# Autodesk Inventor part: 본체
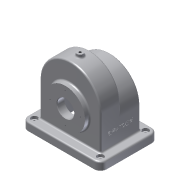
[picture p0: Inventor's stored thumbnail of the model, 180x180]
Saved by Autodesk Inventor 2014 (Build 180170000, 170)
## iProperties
Created: 2017-11
Part Number: 본체
Material: 알루미늄 6061
Document SubType Name: Modeling
Designer: user
Density: 2.71 g/cm^3
Appearance: 알루미늄 - 평지
Mass: 1124.69 g
Surface Area: 1251.26 cm^2
Volume: 415.016 cm^3
Author: user
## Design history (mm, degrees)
sketch "스케치2"
  geometry: L1 (-58, 0)-(-58, -65); L2 (58, 0)-(58, -65); L3 (58, -65)-(-58, -65); A1 r 58 centre (0, 0) between (58, 0) and (-58, 0); 1 further point
  constraints: 6 end point, 2 point on circle, 2 tangent, 1 centre point, 1 coincident, 1 parallel, 1 perpendicular, 1 vertical
  dimensions: "d2" = 116 diameter of A1; "d3" = 65 distance of L1.start L1.end
extrude "돌출1" new body sketch "스케치2" distance "d4" = 38; taper "d5" = 0 deg
sketch "스케치3"
  geometry: L1 (0, 0)-(0, -23); L2 (-58, 0)-(-58, -65) reference; L3 (-58, -65)-(58, -65) reference; L4 (58, -65)-(58, 0) reference; A1 r 58 centre (0, -23) between (58, -23) and (-58, -23)
  constraints: 2 end point, 2 point on circle, 2 point on line, 1 centre point, 1 coincident, 1 vertical
  dimensions: "d7" = 23 distance of L1.start L1.end; "d8" = 116 diameter of A1
extrude "돌출2" join sketch "스케치3" distance "d9" = 38; taper "d10" = 0 deg
sketch "스케치4"
  geometry: L1 (-17, -93)-(133, -93); L2 (133, -93)-(133, 17); L3 (133, 17)-(-17, 17); L4 (-17, 17)-(-17, -93); L5 (-17, -93)-(133, 17); L6 (133, -93)-(-17, 17); 1 further point
  constraints: 12 end point, 2 midpoint, 2 parallel, 1 horizontal, 1 perpendicular
  dimensions: "d11" = 110 distance of L3.end L1.start; "d12" = 150 distance of L1.start L1.end
extrude "돌출3" join sketch "스케치4" distance "d13" = 15; taper "d14" = 0 deg
fillet "모깎기1" dims "d15" = 12
sketch "스케치5"
  geometry: L1 (63, -80)-(-63, -80) reference; L2 (0, -80)-(0, -15); C1 r 37.5 at (0, -15); 1 further point
  constraints: 2 end point, 1 centre point, 1 coincident, 1 midpoint, 1 perpendicular
  dimensions: "d17" = 65 distance of L2.start L2.end; "d18" = 75 diameter of C1
extrude "돌출4" join sketch "스케치5" distance "d19" = 9; taper "d20" = 0 deg
sketch "스케치6"
  geometry: L1 (63, -80)-(-63, -80) reference; L2 (0, -80)-(0, -15); C1 r 31 at (0, -15); 1 further point
  constraints: 2 end point, 1 centre point, 1 coincident, 1 midpoint, 1 perpendicular
  dimensions: "d21" = 65 distance of L2.start L2.end; "d22" = 62 diameter of C1
extrude "돌출5" join sketch "스케치6" distance "d23" = 10; taper "d24" = 0 deg
fillet "모깎기2" dims "d16" = 3
node "작업 평면1"
sketch "스케치8"
  geometry: L1 (-53, 0)-(-53, -89.092); L2 (-53, -89.092)-(53, -89.092); L3 (53, -89.092)-(53, 0); A1 r 53 centre (0, 0) between (53, 0) and (-53, 0); 1 further point
  constraints: 6 end point, 2 point on circle, 2 tangent, 1 centre point, 1 coincident, 1 perpendicular, 1 vertical
  dimensions: "d39" = 106 diameter of A1
extrude "돌출6" cut sketch "스케치8" distance "d40" = 28; taper "d41" = 0 deg
sketch "스케치9"
  geometry: L1 (0, 0)-(0, -23); L2 (-53, -23)-(-53, -80); L3 (-53, -80)-(53, -80); L4 (53, -80)-(53, -23); L5 (-63, -80)-(-75, -80) reference; L6 (-63, -80)-(63, -80) reference; L7 (75, -80)-(63, -80) reference; L8 (63, -80)-(75, -80) reference; L9 (63, -80)-(-63, -80) reference; L10 (-75, -80)-(-63, -80) reference; A1 r 53 centre (0, -23) between (53, -23) and (-53, -23)
  constraints: 8 end point, 2 point on circle, 2 tangent, 1 centre point, 1 coincident, 1 parallel, 1 perpendicular, 1 vertical
  dimensions: "d42" = 23 distance of L1.start L1.end; "d43" = 106 diameter of A1
extrude "돌출7" cut sketch "스케치9" distance "d44" = 38; taper "d45" = 0 deg
sketch "스케치7"
  geometry: L1 (-10.374, 37.577)-(21.813, -22.429); L2 (58, 3)-(58, 35) reference; L3 (22.5, 41)-(22.5, 47) reference; L4 (35, -3)-(35, -35) reference; L5 (16, -41)-(16, -48) reference; L6 (35, -3)-(35, -35) reference; L7 (-80, -55)-(-80, -43) reference; L8 (-80, -43)-(-80, -55) reference; L9 (-80, -43)-(-80, 43) reference; L10 (-80, 55)-(-80, 43) reference; L11 (-80, 43)-(-80, 55) reference; L12 (-80, 43)-(-80, -43) reference; L13 (0, 38)-(-62, 38) reference; L14 (0, 38)-(0, 38) reference; L15 (-62, 38)-(0, 38) reference; L16 (25.5, 38)-(-55.5, 38) reference; L17 (55, 0)-(3.63, 0) reference; L18 (22.5, 47)-(-52.5, 47) reference; L19 (-46, -48)-(16, -48) reference; L20 (-15, -48)-(-15, 47); L21 (1, 47)-(1, 33); L22 (1, 33)-(-15, 33); L23 (1, -48)-(1, -33); L24 (1, -33)-(-15, -33); A1 r 3 centre (55, 35) between (58, 35) and (55, 38) reference; A2 r 3 centre (25.5, 41) between (22.5, 41) and (25.5, 38) reference; A3 r 3 centre (38, -3) between (38, 0) and (35, -3) reference; A4 r 3 centre (55, 3) between (55, 0) and (58, 3) reference; A5 r 3 centre (32, -35) between (32, -38) and (35, -35) reference; A6 r 3 centre (-55.5, 41) between (-55.5, 38) and (-52.5, 41) reference; 1 further point
  constraints: 12 end point, 4 point on line, 3 perpendicular, 2 midpoint, 1 parallel
  dimensions: "d30" = 32 diameter of L21 L20; "d31" = 32 diameter of L23 L20; "d32" = 14 distance of L21.start L21.end; "d33" = 15 distance of L23.start L23.end
revolve "회전1" sketch "스케치7" stored, may be unused: angle "d34" = 90 deg
chamfer "모따기1" distance "d35" = 1; stored, may be unused: second distance "d36" = 2, angle "d37" = 45 deg
fillet "모깎기3" dims "d46" = 3
sketch "스케치10"
  geometry: L1 (53, 19)-(64, 19); L2 (0, 38)-(55, 38) reference; L3 (64, 19)-(64, 13); L4 (64, 13)-(53, 13); L5 (-80, -30)-(-80, 30) reference; L6 (53, 13)-(53, 19); L7 (53, 8)-(53, 30) reference; 2 further points
  constraints: 9 end point, 2 perpendicular, 1 collinear, 1 horizontal, 1 parallel
  dimensions: "d47" = 19 distance between parallel lines of L1 L2; "d48" = 12 diameter of L4 L1; "d49" = 144 distance between parallel lines of L3 L5
revolve "회전2" sketch "스케치10" stored, may be unused: angle "d50" = 90 deg
fillet "모깎기4" dims "d51" = 3
hole "구멍1" diameter "d54" = 4.459; stored, may be unused: countersink angle "d58" = 90 deg, drill point angle "d60" = 0 deg; dims "d55" = 15, "d56" = 4, "d57" = 2, "d59" = 15, "d117" = 10, "d118" = 10
hole "구멍2" diameter "d63" = 5; stored, may be unused: countersink angle "d67" = 90 deg, drill point angle "d69" = 0 deg; dims "d61" = 10, "d62" = 10, "d64" = 5, "d65" = 12, "d66" = 5, "d68" = 5
hole "구멍3" diameter "d72" = 5; stored, may be unused: countersink angle "d76" = 90 deg, drill point angle "d78" = 0 deg; dims "d70" = 10, "d71" = 10, "d73" = 5, "d74" = 12, "d75" = 5, "d77" = 5
hole "구멍4" diameter "d81" = 5; stored, may be unused: countersink angle "d85" = 90 deg, drill point angle "d87" = 0 deg; dims "d79" = 10, "d80" = 10, "d82" = 5, "d83" = 12, "d84" = 5, "d86" = 5
hole "구멍5" diameter "d90" = 5; stored, may be unused: countersink angle "d94" = 90 deg, drill point angle "d96" = 0 deg; dims "d88" = 10, "d89" = 10, "d91" = 5, "d92" = 12, "d93" = 5, "d95" = 5
sketch "스케치13"
  geometry: L1 (-29, 0)-(29, 0); L2 (0, 29)-(0, -29); C1 r 16 at (0, 0) reference; A1 r 29 centre (0, 0) between (-29, 0) and (29, 0); 1 further point
  constraints: 4 end point, 4 point on circle, 1 centre point, 1 coincident, 1 horizontal, 1 perpendicular
  dimensions: "d97" = 58 diameter of A1
hole "구멍6" sketch "스케치13" at (29, 0), (0, 29), (-29, 0), (0, -29) diameter "d98" = 2.459; stored, may be unused: countersink angle "d102" = 90 deg, drill point angle "d104" = 118 deg; dims "d99" = 6, "d100" = 12, "d101" = 5, "d103" = 8
sketch "스케치14"
  geometry: L1 (-26, 0)-(26, 0); L2 (0, 26)-(0, -26); C1 r 16 at (0, 0) reference; A1 r 26 centre (0, 0) between (-26, 0) and (26, 0); 1 further point
  constraints: 4 end point, 4 point on circle, 1 centre point, 1 coincident, 1 horizontal, 1 perpendicular
  dimensions: "d105" = 52 diameter of A1
hole "구멍7" sketch "스케치14" at (0, 26), (-26, 0), (0, -26), (26, 0) diameter "d106" = 2.459; stored, may be unused: countersink angle "d110" = 90 deg, drill point angle "d112" = 118 deg; dims "d107" = 6, "d108" = 12, "d109" = 5, "d111" = 8
sketch "스케치15"
  geometry: L1 (-3, 62)-(-3, 0) reference; L2 (78, -18)-(-8, -18) reference; 2 further points
  constraints: 1 other
  dimensions: "d113" = 38 distance from line of point (35, 22) L1; "d114" = 40 distance from line of point (35, 22) L2
extrude "돌출8" join sketch "스케치15" distance "d115" = 0.5; taper "d116" = 0 deg
node "솔리드1"
node "투영된 루프1"
node "투영된 루프2"
node "투영된 루프3"
other parameters: "d38" = -33
